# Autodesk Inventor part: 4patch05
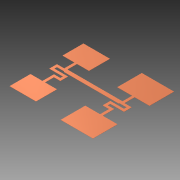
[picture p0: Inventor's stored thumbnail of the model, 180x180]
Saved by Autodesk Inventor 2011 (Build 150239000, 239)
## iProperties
Created: 2014-03
Part Number: 4patch05
Document SubType Name: Modeling
Designer: Evgeny
Density: 1 g/cm^3
Author: Evgeny
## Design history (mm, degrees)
sketch "Эскиз1"
  geometry: L1 (-64.5, 4.5)-(64.5, 4.5); L2 (64.5, -3)-(64.5, -4.5); L3 (64.5, -4.5)-(-64.5, -4.5); L4 (-64.5, -4.5)-(-64.5, -3); L5 (-70.5, 3)-(-72.9, 3); L6 (-81.5, -3)-(-64.5, -3); L7 (-70.5, 3)-(-70.5, 27); L8 (-64.5, 27)-(-64.5, 4.5); L9 (-72.9, 3)-(-87.5, 3); L10 (-87.5, 3)-(-87.5, -14); L11 (-81.5, -9)-(-81.5, -3); L12 (-81.5, -9)-(-49.5, -9); L13 (-49.5, -9)-(-49.5, -25); L14 (-55.5, -15)-(-87.5, -15); L15 (-87.5, -15)-(-87.5, -14); L16 (-55.5, -15)-(-55.5, -21); L17 (-49.5, -27)-(-49.5, -25); L18 (-49.5, -27)-(-64.5, -27); L19 (-70.5, -37)-(-70.5, -21); L20 (-70.5, -21)-(-55.5, -21); L21 (-70.5, -21)-(-57.4, -21); L22 (-64.5, -27)-(-64.5, -48); L23 (-70.5, -48)-(-70.5, -21); L24 (70.5, 3)-(87.5, 3); L25 (87.5, 3)-(87.5, -3); L26 (81.5, -3)-(64.5, -3); L27 (70.5, 3)-(70.5, 27); L28 (64.5, 27)-(64.5, 4.5); L29 (81.5, -3)-(81.5, -9); L30 (85.5, -15)-(87.5, -15); L31 (87.5, -15)-(87.5, -3); L32 (85.5, -15)-(55.5, -15); L33 (49.5, -15)-(49.5, -9); L34 (49.5, -9)-(81.5, -9); L35 (49.5, -9)-(55.5, -9); L36 (55.5, -15)-(55.5, -21); L37 (55.5, -27)-(49.5, -27); L38 (49.5, -27)-(49.5, -9); L39 (55.5, -27)-(64.5, -27); L40 (70.5, -27)-(70.5, -21); L41 (70.5, -21)-(55.5, -21); L42 (70.5, -21)-(65, -21); L43 (64.5, -27)-(64.5, -48); L44 (70.5, -48)-(70.5, -21); L45 (-98.5, 76)-(-36.5, 76); L46 (-36.5, 76)-(-36.5, 27); L47 (-98.5, 27)-(-98.5, 76); L48 (29.75, 84.5)-(105.25, 84.5); L49 (105.25, 84.5)-(105.25, 27); L50 (29.75, 27)-(29.75, 84.5); L51 (-98.5, -97)-(-36.5, -97); L52 (-36.5, -97)-(-36.5, -48); L53 (-98.5, -48)-(-98.5, -97); L54 (29.75, -105.5)-(105.25, -105.5); L55 (105.25, -105.5)-(105.25, -48); L56 (29.75, -48)-(29.75, -105.5); L57 (-36.5, 27)-(-64.5, 27); L58 (-70.5, 27)-(-98.5, 27); L59 (105.25, 27)-(70.5, 27); L60 (64.5, 27)-(29.75, 27); L61 (-36.5, -48)-(-64.5, -48); L62 (-70.5, -48)-(-98.5, -48); L63 (105.25, -48)-(70.5, -48); L64 (64.5, -48)-(29.75, -48); 1 further point
  constraints: 128 end point, 30 parallel, 15 horizontal, 14 perpendicular, 6 collinear
  dimensions: "d0" = 129 distance between parallel lines of L2 L4; "d1" = 64.5 distance from line of point (0, 0) L4; "d2" = 9 distance between parallel lines of L3 L1; "d3" = 4.5 distance from line of point (0, 0) L3; "d5" = 6 distance between parallel lines of L5 L6; "d7" = 6 distance between parallel lines of L7 L8; "d8" = 17 distance from line of L4.end L11; "d9" = 6 distance between parallel lines of L10 L11; "d10" = 6 distance between parallel lines of L12 L6; "d11" = 6 distance between parallel lines of L14 L12; "d12" = 15 distance between parallel lines of L17 L22; "d13" = 6 distance between parallel lines of L17 L16; "d14" = 6 distance between parallel lines of L18 L20; "d15" = 6 distance between parallel lines of L23 L22; "d18" = 64.5 distance from line of L22 point (0, 0); "d19" = 6 distance between parallel lines of L27 L28; "d20" = 17 distance between parallel lines of L29 L2; "d21" = 6 distance between parallel lines of L24 L26; "d22" = 6 distance between parallel lines of L31 L29; "d23" = 6 distance between parallel lines of L32 L34; "d24" = 6 distance between parallel lines of L44 L43; "d25" = 6 distance between parallel lines of L39 L41; "d26" = 6 distance between parallel lines of L38 L36; "d27" = 129 distance between parallel lines of L43 L22; "d28" = 15 distance between parallel lines of L38 L43; "d31" = 62 distance between parallel lines of L47 L46; "d33" = 75.5 distance between parallel lines of L49 L50; "d38" = 62 distance between parallel lines of L52 L53; "d40" = 75.5 distance between parallel lines of L55 L56; "d47" = 1.5 distance between parallel lines of L5 L1; "d48" = 1.5 distance between parallel lines of L24 L1; "d49" = 6 distance between parallel lines of L34 L26; "d50" = 129 distance between parallel lines of L28 L8; "d51" = 64.5 distance from line of L8 point (0, 0); "d52" = 49 distance between parallel lines of L58 L45; "d53" = 49 distance between parallel lines of L51 L62; "d54" = 57.5 distance between parallel lines of L48 L59; "d55" = 57.5 distance between parallel lines of L54 L63; "d56" = 28 distance between parallel lines of L46 L8; "d57" = 34.75 distance between parallel lines of L50 L28
extrude "Выдавливание1" new body sketch "Эскиз1" distance "d43" = 0.5; taper "d44" = 0 deg
node "Твердое тело1"
other parameters: "d32" = 49, "d34" = 57.5, "d37" = 49, "d39" = 57.5, "d45" = 33, "d46" = 33
